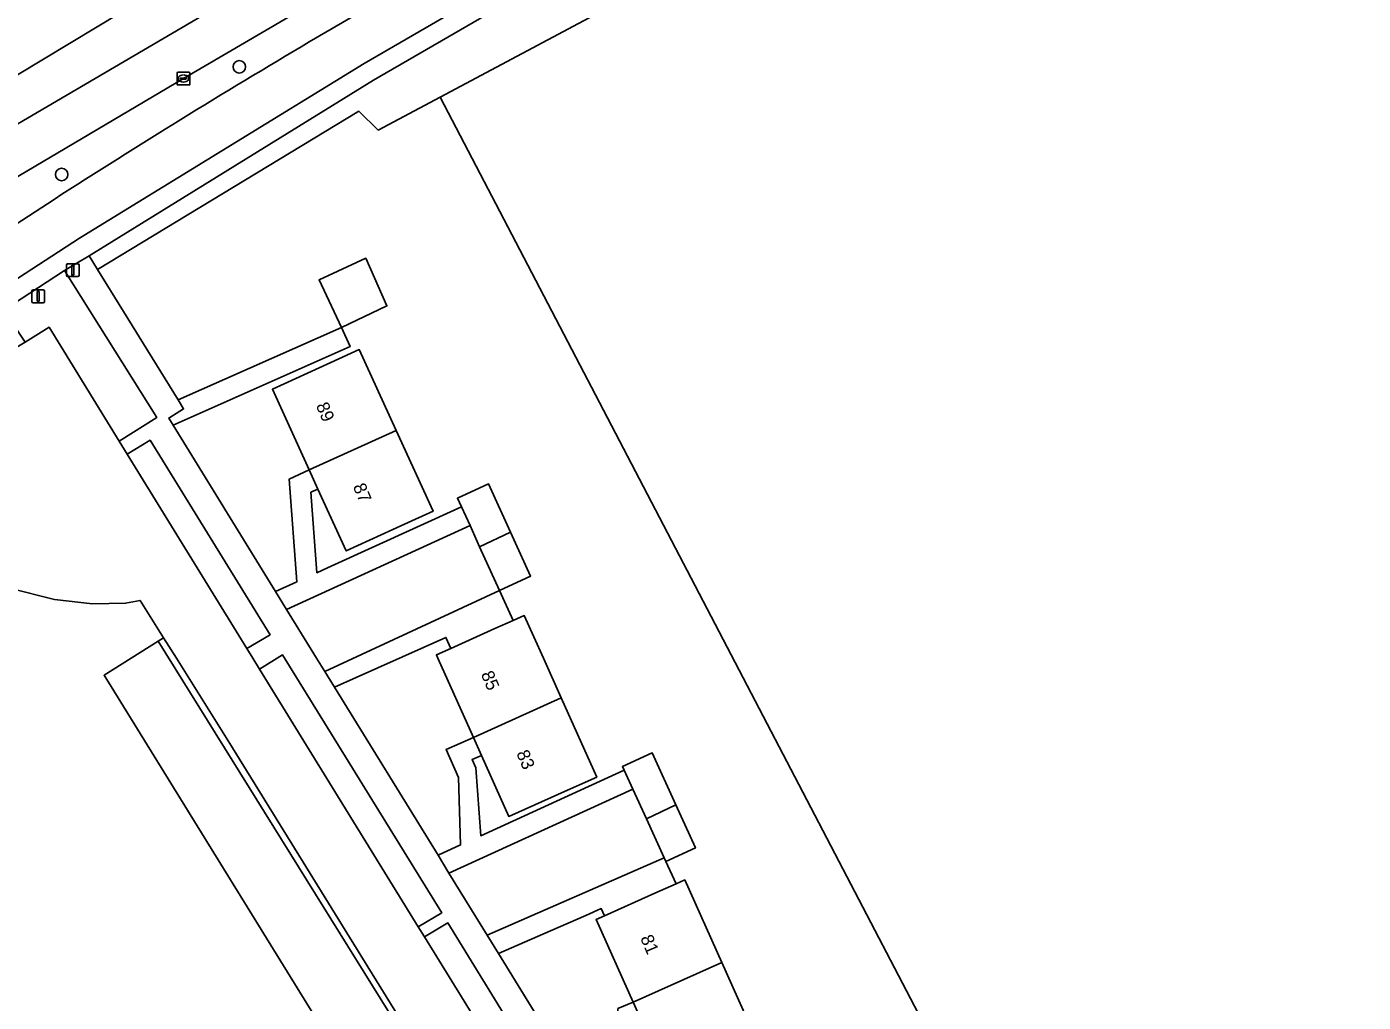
# Model space of a CAD drawing. Extents: x 158132 to 159664, y 385256 to 387218.
# Drawn here: x 158569.7 to 158673.7, y 386973.2 to 387049.2 of the extents above; entities that cross this region are included whole.
import ezdxf

# ---------------------------------------------------------------- set-up
doc = ezdxf.new("R2010")
doc.units = 0
for name, color, linetype in [('IMGEO_Afsluitpaal', 7, 'Continuous'), ('IMGEO_Berm_groen', 7, 'Continuous'), ('IMGEO_Boom', 7, 'Continuous'), ('IMGEO_Erf', 7, 'Continuous'), ('IMGEO_Fietspad_gesloten', 7, 'Continuous'), ('IMGEO_Gemengd_bos', 7, 'Continuous'), ('IMGEO_Groenvoorziening', 7, 'Continuous'), ('IMGEO_Kolk', 7, 'Continuous'), ('IMGEO_Pand', 7, 'Continuous'), ('IMGEO_Pand_nummerreeks', 7, 'Continuous'), ('IMGEO_Parkeervlak_open', 7, 'Continuous'), ('IMGEO_Rijbaan_lokaal_open', 7, 'Continuous'), ('IMGEO_Rijbaan_regionaal_gesloten', 7, 'Continuous'), ('IMGEO_Verkeersbordpaal', 7, 'Continuous'), ('IMGEO_Voetpad_gesloten', 7, 'Continuous'), ('IMGEO_Voetpad_open', 7, 'Continuous')]:
    doc.layers.add(name, color=color, linetype=linetype)

msp = doc.modelspace()

# ---------------------------------------------------------------- linework, layer by layer
at = {"layer": 'IMGEO_Afsluitpaal'}
for p, q in [((158572.78, 387029.82), (158572.78, 387030.62)), ((158572.78, 387030.62), (158572.78, 387029.82)), ((158572.88, 387030.72), (158573.67, 387030.72)), ((158573.67, 387030.72), (158572.88, 387030.72)), ((158573.77, 387030.62), (158573.77, 387029.82)), ((158573.77, 387029.82), (158573.77, 387030.62)), ((158573.67, 387029.72), (158572.88, 387029.72)), ((158572.88, 387029.72), (158573.67, 387029.72))]:
    msp.add_line(p, q, dxfattribs=at)
msp.add_lwpolyline([(158573.2, 387030.6), (158573.35, 387030.6), (158573.35, 387029.85), (158573.2, 387029.85), (158573.2, 387030.6)], dxfattribs=at)
for centre, start, end in [((158572.88, 387030.62), 90, 180), ((158572.88, 387030.62), 90, 180), ((158573.67, 387030.62), 0, 90), ((158573.67, 387030.62), 360, 90), ((158572.88, 387029.82), 180, 270), ((158572.88, 387029.82), 180, 270), ((158573.67, 387029.82), 270, 0), ((158573.67, 387029.82), 270, 0)]:
    msp.add_arc(centre, 0.1, start, end, dxfattribs=at)
at = {"layer": 'IMGEO_Berm_groen'}
for points in [[(158591.69, 387047.99), (158627.16, 387068.6), (158617.16, 387065.84), (158599.21, 387055.3), (158581.9, 387045.14), (158567.26, 387036.49), (158566.68, 387036.17)], [(158544.43, 387017.93), (158571.82, 387035.73)]]:
    msp.add_lwpolyline(points, dxfattribs=at)
msp.add_arc((158908.89, 386511.61), 623.15, 120.5988, 122.74547, dxfattribs=at)
at = {"layer": 'IMGEO_Boom'}
for centre in [(158586.24, 387046.05), (158572.41, 387037.67)]:
    msp.add_circle(centre, 0.489, dxfattribs=at)
at = {"layer": 'IMGEO_Erf'}
msp.add_lwpolyline([(158647.81, 386955.65), (158601.87, 387043.7), (158597.05, 387041.13), (158595.54, 387042.59), (158575.2, 387030.27), (158581.48, 387020.11), (158594.2, 387025.76), (158594.87, 387024.27), (158581.08, 387018.15), (158589.05, 387005.21), (158590.71, 387005.95), (158590.12, 387013.94), (158591.69, 387014.66), (158588.82, 387020.95), (158593.37, 387023.03), (158595.58, 387024.04), (158598.45, 387017.74), (158601.33, 387011.45), (158599.11, 387010.44), (158594.56, 387008.36), (158592.36, 387013.18), (158591.82, 387012.93), (158592.28, 387006.66), (158593.11, 387007.04), (158603.53, 387011.79), (158603.22, 387012.46), (158605.65, 387013.57), (158607.36, 387009.83), (158608.92, 387006.4), (158606.49, 387005.29), (158607.55, 387002.94), (158608.42, 387003.33), (158609.91, 387000), (158611.3, 386996.91), (158614.06, 386990.75), (158611.78, 386989.73), (158607.22, 386987.69), (158605.09, 386992.44), (158604.36, 386992.12), (158604.65, 386991.48), (158605.04, 386986.18), (158616.21, 386991.28), (158616.07, 386991.58), (158618.38, 386992.63), (158620.23, 386988.58), (158621.75, 386985.24), (158619.45, 386984.19), (158620.24, 386982.45), (158620.92, 386982.75), (158623.8, 386976.31), (158626.68, 386969.87)], dxfattribs=at)
for points in [[(158594.2, 387025.76), (158592.45, 387029.47), (158596.08, 387031.15), (158597.73, 387027.43)], [(158606.49, 387005.29), (158604.95, 387008.67), (158604.2, 387010.33), (158589.91, 387003.81), (158592.26, 387000), (158592.89, 386998.98)], [(158601.7, 387000), (158601.58, 387000.26), (158602.72, 387000.77), (158602.32, 387001.63), (158593.65, 386997.74), (158601.71, 386984.66), (158603.47, 386985.47), (158603.31, 386990.72), (158602.34, 386992.89), (158604.46, 386993.84)], [(158617.94, 386987.49), (158616.88, 386989.81), (158602.55, 386983.28), (158605.53, 386978.45), (158619.32, 386984.46)], [(158614.02, 386979.67), (158614.66, 386979.95), (158614.41, 386980.51), (158613.22, 386979.97), (158610.46, 386978.77), (158606.42, 386977.01), (158614.42, 386964.01), (158615.97, 386964.72), (158615.71, 386972.73), (158616.9, 386973.22)]]:
    msp.add_lwpolyline(points, close=True, dxfattribs=at)
at = {"layer": 'IMGEO_Fietspad_gesloten'}
for points in [[(158490.61, 386969.27), (158499.21, 386977.39), (158500, 386978.13), (158506.55, 386984.13), (158513.13, 386989.79), (158514.13, 386990.65), (158525.95, 387000), (158529.92, 387003.03), (158546.1, 387014.7), (158573.79, 387032.7), (158595.96, 387046.32), (158640.94, 387072.39), (158675.02, 387091.93), (158709.57, 387111.62)], [(158640.95, 387076.65), (158639.75, 387075.93), (158627.16, 387068.6), (158591.69, 387047.99)], [(158571.82, 387035.73), (158544.43, 387017.93)]]:
    msp.add_lwpolyline(points, dxfattribs=at)
msp.add_arc((158908.89, 386511.61), 623.15, 120.5988, 122.74547, dxfattribs=at)
at = {"layer": 'IMGEO_Gemengd_bos'}
msp.add_lwpolyline([(158687.81, 387060.41), (158689.82, 387061.16), (158703.82, 387101.71), (158681.04, 387088.11), (158663.51, 387076.57), (158660.41, 387074.96), (158660.01, 387075.7), (158644.04, 387067.33), (158614.63, 387050.48), (158601.87, 387043.7), (158647.81, 386955.65), (158659.44, 386961.72), (158679.26, 386924.45), (158648.61, 386908.46), (158655.38, 386860.52), (158656.73, 386859.94), (158667.25, 386855.4)], dxfattribs=at)
at = {"layer": 'IMGEO_Groenvoorziening'}
for points in [[(158676.28, 387089.71), (158659.17, 387079.77), (158659.55, 387079.09), (158660.81, 387079.73), (158662.26, 387077.17), (158659.69, 387075.72), (158658.24, 387078.28), (158658.74, 387078.62), (158658.37, 387079.32), (158644.61, 387071.6), (158644.09, 387072.48), (158596.69, 387045), (158574.56, 387031.33), (158575.2, 387030.27), (158595.54, 387042.59), (158597.05, 387041.13), (158601.87, 387043.7), (158614.63, 387050.48), (158644.04, 387067.33), (158660.01, 387075.7), (158660.41, 387074.96), (158663.51, 387076.57), (158681.04, 387088.11)], [(158594.65, 386968.03), (158575.72, 386998.68), (158579.93, 387001.32), (158580.35, 387001.58), (158578.52, 387004.51), (158577.39, 387004.29), (158574.81, 387004.23), (158571.86, 387004.58), (158568.36, 387005.47), (158564.89, 387006.54), (158561.68, 387007.69), (158556.62, 387015.67), (158567.71, 387023.13), (158567.57, 387023.39), (158565.98, 387025.84), (158546.88, 387013.42), (158530.82, 387001.85), (158528.38, 387000), (158515.07, 386989.48), (158514.05, 386988.61), (158507.53, 386983.02), (158500.23, 386976.33), (158500, 386976.11), (158490.27, 386966.83)]]:
    msp.add_lwpolyline(points, dxfattribs=at)
for points in [[(158567.92, 387027.11), (158569.56, 387024.62), (158571.43, 387025.78), (158576.89, 387016.9), (158579.82, 387018.76), (158572.64, 387030.18)], [(158579.3, 387016.97), (158577.5, 387015.89), (158586.83, 387000.75), (158588.64, 387001.83)], [(158589.61, 387000.26), (158587.81, 386999.16), (158600.17, 386979.09), (158602, 386980.19)], [(158615.26, 386958.58), (158614.78, 386959.36), (158602.48, 386979.4), (158600.65, 386978.31), (158613, 386958.27), (158613.49, 386957.48), (158625.65, 386937.74), (158627.4, 386938.84)]]:
    msp.add_lwpolyline(points, close=True, dxfattribs=at)
at = {"layer": 'IMGEO_Kolk'}
for p, q in [((158581.4, 387044.71), (158581.4, 387045.56)), ((158581.47, 387045.64), (158582.32, 387045.64)), ((158581.66, 387045.13), (158581.66, 387045.14)), ((158581.7, 387045.18), (158582.1, 387045.18)), ((158582.09, 387045.09), (158581.7, 387045.09)), ((158581.91, 387044.86), (158581.88, 387044.86)), ((158581.89, 387045.42), (158581.91, 387045.42)), ((158582.14, 387045.14), (158582.14, 387045.13)), ((158582.4, 387045.56), (158582.4, 387044.71)), ((158582.32, 387044.64), (158581.47, 387044.64))]:
    msp.add_line(p, q, dxfattribs=at)
for points in [[(158581.4, 387044.71), (158581.4, 387045.56)], [(158581.47, 387045.64), (158582.32, 387045.64)], [(158582.4, 387045.56), (158582.4, 387044.71)], [(158582.32, 387044.64), (158581.47, 387044.64)]]:
    msp.add_lwpolyline(points, dxfattribs=at)
for centre, radius, start, end in [((158581.47, 387045.56), 0.0765, 91.552, 178.448), ((158581.47, 387045.56), 0.0765, 91.552, 178.448), ((158581.7, 387045.14), 0.0403, 85.8775, 175.7526), ((158581.69, 387045.13), 0.0366, 178.938, 274.7102), ((158582.1, 387045.14), 0.043, 264.8664, 352.4533), ((158582.1, 387045.14), 0.0386, 1.7309, 96.639), ((158582.32, 387045.56), 0.0765, 1.552, 88.448), ((158582.32, 387045.56), 0.0765, 1.552, 88.448), ((158581.47, 387044.71), 0.0765, 181.552, 268.448), ((158581.47, 387044.71), 0.0765, 181.552, 268.448), ((158582.32, 387044.71), 0.0765, 271.552, 358.448), ((158582.32, 387044.71), 0.0765, 271.552, 358.448)]:
    msp.add_arc(centre, radius, start, end, dxfattribs=at)
for centre, major_axis, ratio, start_param, end_param in [((158581.88, 387045.14), (-0.387, 0.002), 0.722429, 4.712389, 7.853982), ((158581.91, 387045.14), (-0.39, 0.002), 0.717154, 1.570796, 4.712389)]:
    msp.add_ellipse(centre, major_axis=major_axis, ratio=ratio, start_param=start_param, end_param=end_param, dxfattribs=at)
at = {"layer": 'IMGEO_Pand'}
for points in [[(158597.73, 387027.43), (158596.08, 387031.15), (158592.45, 387029.47), (158594.2, 387025.76)], [(158591.69, 387014.66), (158598.45, 387017.74), (158595.58, 387024.04), (158593.37, 387023.03), (158588.82, 387020.95)], [(158598.45, 387017.74), (158591.69, 387014.66), (158592.36, 387013.18), (158594.56, 387008.36), (158599.11, 387010.44), (158601.33, 387011.45)], [(158605.65, 387013.57), (158603.22, 387012.46), (158603.53, 387011.79), (158604.2, 387010.33), (158604.95, 387008.67), (158607.36, 387009.83)], [(158608.92, 387006.4), (158607.36, 387009.83), (158604.95, 387008.67), (158606.49, 387005.29)], [(158609.91, 387000), (158608.42, 387003.33), (158607.55, 387002.94), (158606.14, 387002.31), (158602.72, 387000.77), (158601.58, 387000.26), (158601.7, 387000), (158604.46, 386993.84), (158611.3, 386996.91)], [(158611.3, 386996.91), (158604.46, 386993.84), (158605.09, 386992.44), (158607.22, 386987.69), (158611.78, 386989.73), (158614.06, 386990.75)], [(158618.38, 386992.63), (158616.07, 386991.58), (158616.21, 386991.28), (158616.88, 386989.81), (158617.94, 386987.49), (158620.23, 386988.58)], [(158620.23, 386988.58), (158617.94, 386987.49), (158619.32, 386984.46), (158619.45, 386984.19), (158621.75, 386985.24)], [(158620.92, 386982.75), (158620.24, 386982.45), (158618.58, 386981.71), (158614.66, 386979.95), (158614.02, 386979.67), (158616.9, 386973.22), (158623.8, 386976.31)], [(158623.8, 386976.31), (158616.9, 386973.22), (158617.49, 386971.89), (158619.78, 386966.78), (158624.35, 386968.82), (158626.68, 386969.87)]]:
    msp.add_lwpolyline(points, close=True, dxfattribs=at)
at = {"layer": 'IMGEO_Parkeervlak_open'}
msp.add_lwpolyline([(158579.93, 387001.32), (158575.72, 386998.68), (158594.65, 386968.03), (158598.96, 386970.68), (158598.52, 386971.41)], close=True, dxfattribs=at)
at = {"layer": 'IMGEO_Rijbaan_lokaal_open'}
for points in [[(158577.5, 387015.89), (158576.89, 387016.9), (158571.43, 387025.78), (158569.56, 387024.62), (158568.02, 387023.67), (158567.57, 387023.39), (158567.71, 387023.13), (158556.62, 387015.67), (158561.68, 387007.69), (158564.89, 387006.54), (158568.36, 387005.47), (158571.86, 387004.58), (158574.81, 387004.23), (158577.39, 387004.29), (158578.52, 387004.51), (158580.35, 387001.58), (158581.34, 387000), (158585.64, 386993.16), (158585.72, 386993.03), (158634.35, 386914.28)], [(158644.67, 386906.58), (158638.49, 386916.84), (158637.23, 386918.93), (158636.39, 386920.31), (158635.9, 386921.1), (158626.11, 386936.99), (158625.65, 386937.74), (158613.49, 386957.48), (158613, 386958.27), (158600.65, 386978.31), (158600.17, 386979.09), (158587.81, 386999.16), (158587.29, 387000), (158586.83, 387000.75), (158577.5, 387015.89)], [(158585.72, 386993.03), (158585.64, 386993.16), (158581.34, 387000), (158580.35, 387001.58), (158579.93, 387001.32), (158598.52, 386971.41), (158598.96, 386970.68), (158599.26, 386970.21), (158600.56, 386968.1), (158600.95, 386967.46), (158601.32, 386966.86), (158603.95, 386962.59), (158604.58, 386961.57), (158615.46, 386943.91), (158624.24, 386929.68), (158625.84, 386927.1), (158633.99, 386913.88), (158634.88, 386912.07)], [(158634.35, 386914.28), (158585.72, 386993.03)]]:
    msp.add_lwpolyline(points, dxfattribs=at)
at = {"layer": 'IMGEO_Rijbaan_regionaal_gesloten'}
for points in [[(158636.6, 387081.34), (158634.99, 387084.15), (158606.55, 387067.54), (158577.06, 387050.31), (158556.67, 387038.04), (158547.18, 387032.06), (158544.81, 387030.2), (158504.77, 387000.52), (158504.06, 387000), (158500.56, 386997.41), (158500, 386996.98)], [(158565.6, 387047.52), (158547.18, 387032.06), (158556.67, 387038.04), (158577.06, 387050.31), (158606.55, 387067.54), (158634.99, 387084.15)], [(158474.04, 386970.82), (158477.34, 386973.82), (158493.05, 386986.92), (158499.53, 386992.01), (158505.63, 386996.55), (158527.37, 387012.74), (158544.14, 387025.14), (158550.02, 387029.42), (158555.12, 387033.01), (158561.93, 387037.34), (158568.26, 387041.17), (158601.79, 387060.88), (158615.07, 387068.69), (158636.6, 387081.34)], [(158566.68, 387036.17), (158567.26, 387036.49), (158581.9, 387045.14), (158599.21, 387055.3), (158617.16, 387065.84), (158637.26, 387077.65), (158638.36, 387078.28), (158636.6, 387081.34), (158615.07, 387068.69), (158601.79, 387060.88), (158568.26, 387041.17), (158561.93, 387037.34), (158555.12, 387033.01), (158550.02, 387029.42), (158544.14, 387025.14), (158527.37, 387012.74), (158505.63, 386996.55), (158499.53, 386992.01), (158493.05, 386986.92), (158477.34, 386973.82), (158474.04, 386970.82)]]:
    msp.add_lwpolyline(points, dxfattribs=at)
at = {"layer": 'IMGEO_Verkeersbordpaal'}
for p, q in [((158570.09, 387027.78), (158570.09, 387028.58)), ((158570.09, 387028.58), (158570.09, 387027.78)), ((158570.19, 387028.68), (158570.98, 387028.68)), ((158570.98, 387028.68), (158570.19, 387028.68)), ((158571.08, 387028.58), (158571.08, 387027.78)), ((158571.08, 387027.78), (158571.08, 387028.58)), ((158570.98, 387027.68), (158570.19, 387027.68)), ((158570.19, 387027.68), (158570.98, 387027.68))]:
    msp.add_line(p, q, dxfattribs=at)
msp.add_lwpolyline([(158570.51, 387028.55), (158570.66, 387028.55), (158570.66, 387027.8), (158570.51, 387027.8), (158570.51, 387028.55)], dxfattribs=at)
for centre, start, end in [((158570.19, 387028.58), 90, 180), ((158570.19, 387028.58), 90, 180), ((158570.98, 387028.58), 0, 90), ((158570.98, 387028.58), 360, 90), ((158570.19, 387027.78), 180, 270), ((158570.19, 387027.78), 180, 270), ((158570.98, 387027.78), 270, 0), ((158570.98, 387027.78), 270, 0)]:
    msp.add_arc(centre, 0.1, start, end, dxfattribs=at)
at = {"layer": 'IMGEO_Voetpad_gesloten'}
for points in [[(158774.25, 387147.16), (158777.85, 387149.12), (158796.65, 387159.48), (158826.07, 387175.67), (158824.96, 387177.23), (158823.8, 387176.6), (158776.89, 387150.89), (158732.48, 387123.89), (158722.89, 387118.52), (158715.76, 387114.9), (158709.57, 387111.62), (158675.02, 387091.93), (158640.94, 387072.39), (158595.96, 387046.32), (158573.79, 387032.7), (158546.1, 387014.7), (158529.92, 387003.03), (158525.95, 387000), (158514.13, 386990.65), (158513.13, 386989.79), (158506.55, 386984.13), (158500, 386978.13), (158499.21, 386977.39), (158490.61, 386969.27)], [(158490.27, 386966.83), (158500, 386976.11), (158500.23, 386976.33), (158507.53, 386983.02), (158514.05, 386988.61), (158515.07, 386989.48), (158528.38, 387000), (158530.82, 387001.85), (158546.88, 387013.42), (158565.98, 387025.84), (158566.37, 387026.1), (158567.92, 387027.11), (158572.64, 387030.18), (158574.56, 387031.33), (158596.69, 387045), (158644.09, 387072.48), (158644.61, 387071.6), (158658.37, 387079.32), (158658.74, 387078.62), (158659.55, 387079.09), (158659.17, 387079.77), (158676.28, 387089.71), (158679.07, 387091.31), (158713.23, 387110.71)], [(158614.42, 386964.01), (158606.42, 386977.01), (158605.53, 386978.45), (158602.55, 386983.28), (158601.71, 386984.66), (158593.65, 386997.74), (158592.89, 386998.98), (158592.26, 387000), (158589.91, 387003.81), (158589.05, 387005.21), (158581.08, 387018.15), (158580.75, 387018.7), (158581.9, 387019.42), (158581.48, 387020.11), (158575.2, 387030.27), (158574.56, 387031.33), (158572.64, 387030.18), (158579.82, 387018.76), (158576.89, 387016.9), (158577.5, 387015.89), (158579.3, 387016.97), (158588.64, 387001.83), (158586.83, 387000.75), (158587.29, 387000), (158587.81, 386999.16), (158589.61, 387000.26), (158602, 386980.19), (158600.17, 386979.09), (158600.65, 386978.31), (158602.48, 386979.4), (158614.78, 386959.36)]]:
    msp.add_lwpolyline(points, dxfattribs=at)
at = {"layer": 'IMGEO_Voetpad_open'}
for points in [[(158594.2, 387025.76), (158581.48, 387020.11), (158581.9, 387019.42), (158580.75, 387018.7), (158581.08, 387018.15), (158594.87, 387024.27)], [(158604.2, 387010.33), (158603.53, 387011.79), (158593.11, 387007.04), (158592.28, 387006.66), (158591.82, 387012.93), (158592.36, 387013.18), (158591.69, 387014.66), (158590.12, 387013.94), (158590.71, 387005.95), (158589.05, 387005.21), (158589.91, 387003.81)], [(158606.49, 387005.29), (158592.89, 386998.98), (158593.65, 386997.74), (158602.32, 387001.63), (158602.72, 387000.77), (158606.14, 387002.31), (158607.55, 387002.94)], [(158616.88, 386989.81), (158616.21, 386991.28), (158605.04, 386986.18), (158604.65, 386991.48), (158604.36, 386992.12), (158605.09, 386992.44), (158604.46, 386993.84), (158602.34, 386992.89), (158603.31, 386990.72), (158603.47, 386985.47), (158601.71, 386984.66), (158602.55, 386983.28)], [(158620.24, 386982.45), (158619.45, 386984.19), (158619.32, 386984.46), (158605.53, 386978.45), (158606.42, 386977.01), (158610.46, 386978.77), (158613.22, 386979.97), (158614.41, 386980.51), (158614.66, 386979.95), (158618.58, 386981.71)], [(158629.61, 386969.17), (158628.95, 386970.64), (158617.54, 386965.43), (158617.08, 386971.7), (158617.49, 386971.89), (158616.9, 386973.22), (158615.71, 386972.73), (158615.97, 386964.72), (158614.42, 386964.01), (158615.27, 386962.63)]]:
    msp.add_lwpolyline(points, close=True, dxfattribs=at)

# ---------------------------------------------------------------- texts
at = {"layer": 'IMGEO_Pand_nummerreeks'}
for s, rotation, p in [('89', 292.9781, (158592.19, 387019.68)), ('87', 292.9754, (158595.07, 387013.38)), ('85', 292.9754, (158605.03, 386998.77)), ('83', 292.9754, (158607.79, 386992.61)), ('81', 292.9754, (158617.44, 386978.22))]:
    msp.add_text(s, height=1, rotation=rotation, dxfattribs=at).set_placement(p)

doc.saveas('drawing.dxf')
